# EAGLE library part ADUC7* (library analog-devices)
Precision Analog Microcontroller 12-bit Analog I/O, ARM7TDMI® MCU ADuC7026/27 Source: Source: http://www.analog.com/UploadedFiles/Data_Sheets/288945048AD7C7019_20_1_2_4_5_6_7_0.pdf
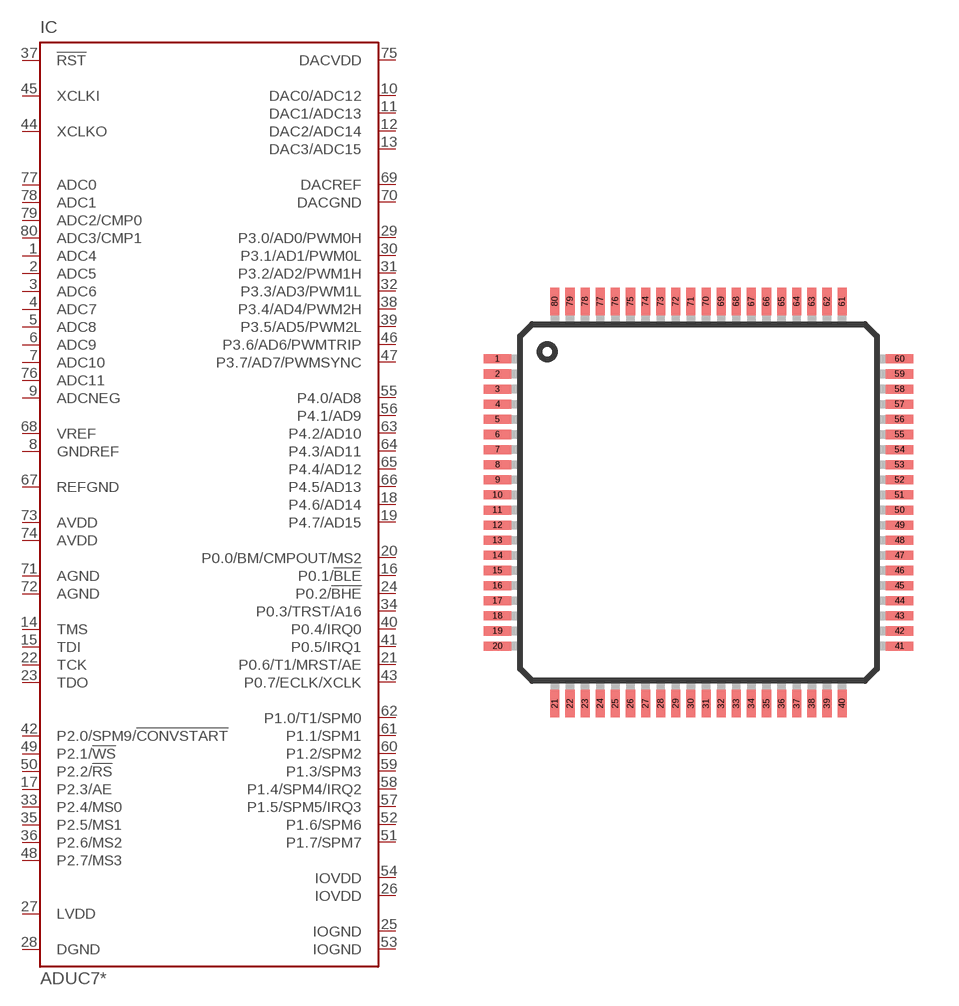
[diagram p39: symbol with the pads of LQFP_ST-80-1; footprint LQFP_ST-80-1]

Designator prefix IC

## ADUC7026BSTZ62 (MPN: ADUC7026BSTZ62; OC_FARNELL: unknown; OC_NEWARK: 12M8346), ADUC7026BSTZ62-RL (OC_FARNELL: unknown; OC_NEWARK: unknown), ADUC7026BSTZ62I (MPN: ADUC7026BSTZ62I-RL; OC_FARNELL: 1162647; OC_NEWARK: 12M8348), ADUC7026BSTZ62I-RL (OC_FARNELL: unknown; OC_NEWARK: unknown), ADUC7027BSTZ62 (MPN: ADUC7027BSTZ62; OC_FARNELL: 1162648; OC_NEWARK: 19M0746), ADUC7027BSTZ62-RL (MPN: ADUC7027BSTZ62-RL; OC_FARNELL: unknown; OC_NEWARK: 12M8350)  [LQFP_ST-80-1]
1  ADC4  in
2  ADC5  in
3  ADC6  in
4  ADC7  in
5  ADC8  in
6  ADC9  in
7  ADC10  in
8  GNDREF  in
9  ADCNEG  in
10  DAC0/ADC12  in
11  DAC1/ADC13  in
12  DAC2/ADC14  in
13  DAC3/ADC15  in
14  TMS  in
15  TDI  in
16  P0.1/!BLE
17  P2.3/AE
18  P4.6/AD14
19  P4.7/AD15
20  P0.0/BM/CMPOUT/MS2
21  P0.6/T1/MRST/AE
22  TCK  in
23  TDO  out
24  P0.2/!BHE
25  IOGND  pwr
26  IOVDD  pwr
27  LVDD  out
28  DGND  pwr
29  P3.0/AD0/PWM0H  out
30  P3.1/AD1/PWM0L  out
31  P3.2/AD2/PWM1H  out
32  P3.3/AD3/PWM1L  out
33  P2.4/MS0
34  P0.3/TRST/A16
35  P2.5/MS1
36  P2.6/MS2
37  !RST  in
38  P3.4/AD4/PWM2H  out
39  P3.5/AD5/PWM2L  out
40  P0.4/IRQ0
41  P0.5/IRQ1
42  P2.0/SPM9/!CONVSTART
43  P0.7/ECLK/XCLK
44  XCLKO  out
45  XCLKI  in
46  P3.6/AD6/PWMTRIP  out
47  P3.7/AD7/PWMSYNC  out
48  P2.7/MS3
49  P2.1/!WS
50  P2.2/!RS
51  P1.7/SPM7
52  P1.6/SPM6
53  IOGND  pwr
54  IOVDD  pwr
55  P4.0/AD8
56  P4.1/AD9
57  P1.5/SPM5/IRQ3
58  P1.4/SPM4/IRQ2
59  P1.3/SPM3
60  P1.2/SPM2
61  P1.1/SPM1
62  P1.0/T1/SPM0
63  P4.2/AD10
64  P4.3/AD11
65  P4.4/AD12
66  P4.5/AD13
67  REFGND  in
68  VREF  pas
69  DACREF  in
70  DACGND  pwr
71  AGND  pwr
72  AGND  pwr
73  AVDD  pwr
74  AVDD  pwr
75  DACVDD  pwr
76  ADC11  in
77  ADC0  in
78  ADC1  in
79  ADC2/CMP0  in
80  ADC3/CMP1  in

## Footprint LQFP_ST-80-1 (pad centres in mm)
80-Lead Low Profile Quad Flat Package (ST-80-1) COMPLIANT TO JEDEC STANDARDS MS-026-BDD Source: http://www.analog.com/UploadedFiles/Data_Sheets/288945048AD7C7019_20_1_2_4_5_6_7_0.pdf
smd 0.9 x 0.3: 1 -6.65,4.75; 2 -6.65,4.25; 3 -6.65,3.75; 4 -6.65,3.25; 5 -6.65,2.75; 6 -6.65,2.25; 7 -6.65,1.75; 8 -6.65,1.25; 9 -6.65,0.75; 10 -6.65,0.25; 11 -6.65,-0.25; 12 -6.65,-0.75; 13 -6.65,-1.25; 14 -6.65,-1.75; 15 -6.65,-2.25; 16 -6.65,-2.75; 17 -6.65,-3.25; 18 -6.65,-3.75; 19 -6.65,-4.25; 20 -6.65,-4.75; 41 6.65,-4.75; 42 6.65,-4.25; 43 6.65,-3.75; 44 6.65,-3.25; 45 6.65,-2.75; 46 6.65,-2.25; 47 6.65,-1.75; 48 6.65,-1.25; 49 6.65,-0.75; 50 6.65,-0.25; 51 6.65,0.25; 52 6.65,0.75; 53 6.65,1.25; 54 6.65,1.75; 55 6.65,2.25; 56 6.65,2.75; 57 6.65,3.25; 58 6.65,3.75; 59 6.65,4.25; 60 6.65,4.75
smd 0.3 x 0.9: 21 -4.75,-6.65; 22 -4.25,-6.65; 23 -3.75,-6.65; 24 -3.25,-6.65; 25 -2.75,-6.65; 26 -2.25,-6.65; 27 -1.75,-6.65; 28 -1.25,-6.65; 29 -0.75,-6.65; 30 -0.25,-6.65; 31 0.25,-6.65; 32 0.75,-6.65; 33 1.25,-6.65; 34 1.75,-6.65; 35 2.25,-6.65; 36 2.75,-6.65; 37 3.25,-6.65; 38 3.75,-6.65; 39 4.25,-6.65; 40 4.75,-6.65; 61 4.75,6.65; 62 4.25,6.65; 63 3.75,6.65; 64 3.25,6.65; 65 2.75,6.65; 66 2.25,6.65; 67 1.75,6.65; 68 1.25,6.65; 69 0.75,6.65; 70 0.25,6.65; 71 -0.25,6.65; 72 -0.75,6.65; 73 -1.25,6.65; 74 -1.75,6.65; 75 -2.25,6.65; 76 -2.75,6.65; 77 -3.25,6.65; 78 -3.75,6.65; 79 -4.25,6.65; 80 -4.75,6.65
